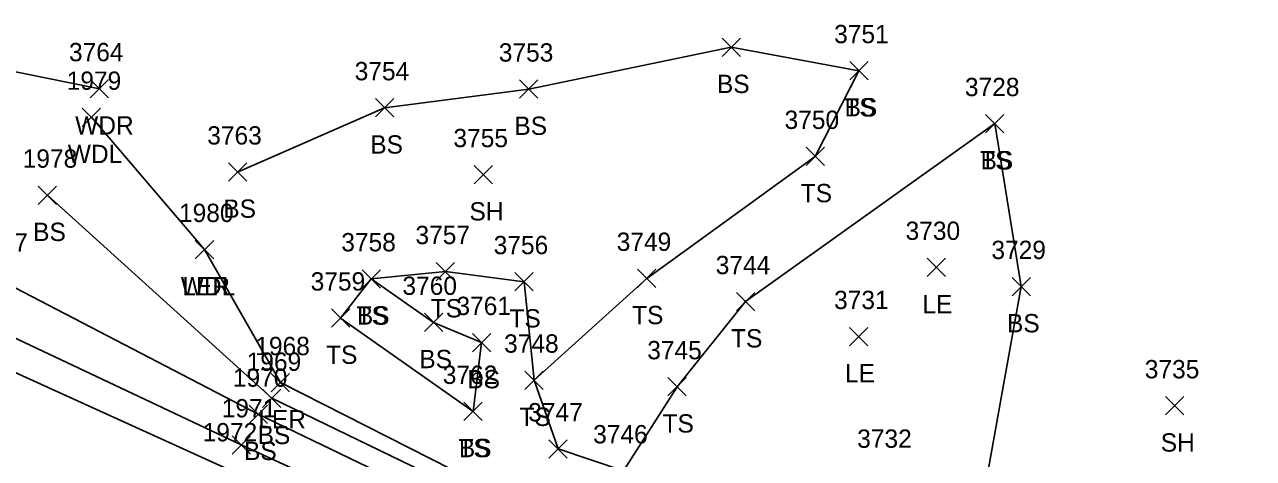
# Model space of a CAD drawing. Extents: x 1599569 to 1610055, y 642560 to 647860.
# Drawn here: x 1601517.7 to 1601651.7, y 647372.7 to 647420 of the extents above; entities that cross this region are included whole.
import ezdxf

# ---------------------------------------------------------------- set-up
doc = ezdxf.new("R2010")
doc.units = 0
for name, color, linetype in [('L_A', 7, 'Continuous'), ('L_I', 7, 'Continuous'), ('L_TIC', 7, 'Continuous'), ('LARO', 7, 'Continuous'), ('LAWA', 7, 'Continuous'), ('LELB', 7, 'Continuous'), ('P_I', 7, 'Continuous'), ('PSP', 7, 'Continuous')]:
    doc.layers.add(name, color=color, linetype=linetype)

msp = doc.modelspace()

# ---------------------------------------------------------------- linework, layer by layer
at = {"layer": 'L_TIC'}
for points in [[(1601593.73, 647416.56), (1601595.73, 647418.56)], [(1601595.73, 647416.56), (1601593.73, 647418.56)], [(1601607.65, 647414), (1601609.65, 647416)], [(1601609.65, 647414), (1601607.65, 647416)], [(1601607.65, 647414), (1601609.65, 647416)], [(1601609.65, 647414), (1601607.65, 647416)], [(1601524.81, 647412.03), (1601526.81, 647414.03)], [(1601526.81, 647412.03), (1601524.81, 647414.03)], [(1601571.64, 647411.99), (1601573.64, 647413.99)], [(1601573.64, 647411.99), (1601571.64, 647413.99)], [(1601555.92, 647409.95), (1601557.92, 647411.95)], [(1601557.92, 647409.95), (1601555.92, 647411.95)], [(1601523.95, 647408.91), (1601525.95, 647410.91)], [(1601525.95, 647408.91), (1601523.95, 647410.91)], [(1601622.48, 647408.22), (1601624.48, 647410.22)], [(1601624.48, 647408.22), (1601622.48, 647410.22)], [(1601622.48, 647408.22), (1601624.48, 647410.22)], [(1601624.48, 647408.22), (1601622.48, 647410.22)], [(1601602.9, 647404.64), (1601604.9, 647406.64)], [(1601604.9, 647404.64), (1601602.9, 647406.64)], [(1601539.89, 647402.94), (1601541.89, 647404.94)], [(1601541.89, 647402.94), (1601539.89, 647404.94)], [(1601566.69, 647402.65), (1601568.69, 647404.65)], [(1601568.69, 647402.65), (1601566.69, 647404.65)], [(1601519.15, 647400.41), (1601521.15, 647402.41)], [(1601521.15, 647400.41), (1601519.15, 647402.41)], [(1601536.28, 647394.48), (1601538.28, 647396.48)], [(1601538.28, 647394.48), (1601536.28, 647396.48)], [(1601536.28, 647394.48), (1601538.28, 647396.48)], [(1601538.28, 647394.48), (1601536.28, 647396.48)], [(1601616.09, 647392.53), (1601618.09, 647394.53)], [(1601618.09, 647392.53), (1601616.09, 647394.53)], [(1601554.46, 647391.28), (1601556.46, 647393.28)], [(1601556.46, 647391.28), (1601554.46, 647393.28)], [(1601554.46, 647391.28), (1601556.46, 647393.28)], [(1601556.46, 647391.28), (1601554.46, 647393.28)], [(1601562.55, 647392.07), (1601564.55, 647394.07)], [(1601564.55, 647392.07), (1601562.55, 647394.07)], [(1601584.51, 647391.33), (1601586.51, 647393.33)], [(1601586.51, 647391.33), (1601584.51, 647393.33)], [(1601571.13, 647390.97), (1601573.13, 647392.97)], [(1601573.13, 647390.97), (1601571.13, 647392.97)], [(1601625.37, 647390.44), (1601627.37, 647392.44)], [(1601627.37, 647390.44), (1601625.37, 647392.44)], [(1601595.3, 647388.79), (1601597.3, 647390.79)], [(1601597.3, 647388.79), (1601595.3, 647390.79)], [(1601551.13, 647387), (1601553.13, 647389)], [(1601553.13, 647387), (1601551.13, 647389)], [(1601561.27, 647386.53), (1601563.27, 647388.53)], [(1601563.27, 647386.53), (1601561.27, 647388.53)], [(1601607.64, 647384.98), (1601609.64, 647386.98)], [(1601609.64, 647384.98), (1601607.64, 647386.98)], [(1601566.5, 647384.33), (1601568.5, 647386.33)], [(1601568.5, 647384.33), (1601566.5, 647386.33)], [(1601544.56, 647379.95), (1601546.56, 647381.95)], [(1601546.56, 647379.95), (1601544.56, 647381.95)], [(1601572.22, 647380.22), (1601574.22, 647382.22)], [(1601574.22, 647380.22), (1601572.22, 647382.22)], [(1601572.22, 647380.22), (1601574.22, 647382.22)], [(1601574.22, 647380.22), (1601572.22, 647382.22)], [(1601587.83, 647379.5), (1601589.83, 647381.5)], [(1601589.83, 647379.5), (1601587.83, 647381.5)], [(1601543.62, 647378.24), (1601545.62, 647380.24)], [(1601545.62, 647378.24), (1601543.62, 647380.24)], [(1601542.15, 647376.5), (1601544.15, 647378.5)], [(1601544.15, 647376.5), (1601542.15, 647378.5)], [(1601565.58, 647376.81), (1601567.58, 647378.81)], [(1601567.58, 647376.81), (1601565.58, 647378.81)], [(1601565.58, 647376.81), (1601567.58, 647378.81)], [(1601567.58, 647376.81), (1601565.58, 647378.81)], [(1601642.1, 647377.42), (1601644.1, 647379.42)], [(1601644.1, 647377.42), (1601642.1, 647379.42)], [(1601540.29, 647373.16), (1601542.29, 647375.16)], [(1601542.29, 647373.16), (1601540.29, 647375.16)], [(1601574.85, 647372.72), (1601576.85, 647374.72)], [(1601576.85, 647372.72), (1601574.85, 647374.72)]]:
    msp.add_lwpolyline(points, dxfattribs=at)
at = {"layer": 'LARO'}
msp.add_lwpolyline([(1601626.48, 647355.02), (1601614.89, 647351.58), (1601573.63, 647366.69), (1601545.56, 647380.95), (1601537.28, 647395.48)], dxfattribs=at)
at = {"layer": 'LAWA'}
for points in [[(1601525.81, 647413.03), (1601511.96, 647415.82), (1601500.19, 647411.74)], [(1601524.95, 647409.91), (1601537.28, 647395.48)]]:
    msp.add_lwpolyline(points, dxfattribs=at)
at = {"layer": 'LELB'}
for points in [[(1601608.65, 647415), (1601594.73, 647417.56), (1601572.64, 647412.99), (1601556.92, 647410.95), (1601540.89, 647403.94)], [(1601573.22, 647381.22), (1601585.51, 647392.33), (1601603.9, 647405.64), (1601608.65, 647415)], [(1601623.48, 647409.22), (1601596.3, 647389.79), (1601588.83, 647380.5), (1601582.98, 647371.32), (1601575.85, 647373.72), (1601573.22, 647381.22), (1601572.13, 647391.97), (1601563.55, 647393.07), (1601555.46, 647392.28), (1601552.13, 647388), (1601566.58, 647377.81)], [(1601623.48, 647409.22), (1601626.37, 647391.44), (1601621.83, 647366.32)], [(1601850.43, 647302.21), (1601817.07, 647284.74), (1601803.58, 647280.33), (1601784.13, 647281.69), (1601758.75, 647290.86), (1601723.07, 647307), (1601685.47, 647323.96), (1601675.62, 647324.78), (1601658.01, 647334.35), (1601634.9, 647343.88), (1601612.64, 647349.36), (1601572.76, 647365.6), (1601544.62, 647379.24), (1601520.15, 647401.41)], [(1601803.11, 647261.21), (1601778.68, 647271.51), (1601755.32, 647284.83), (1601720.1, 647301.53), (1601682.66, 647319.41), (1601674.11, 647321.15), (1601654.95, 647329.02), (1601631.94, 647340.27), (1601610.73, 647346.29), (1601571.98, 647363.61), (1601543.15, 647377.5), (1601514.76, 647392.23)], [(1601555.46, 647392.28), (1601562.27, 647387.53), (1601567.5, 647385.33), (1601566.58, 647377.81)], [(1601677.57, 647312.89), (1601653.54, 647324.67), (1601629.05, 647335.74), (1601609.04, 647344.07), (1601570.72, 647360.58), (1601541.29, 647374.16), (1601512.39, 647387.81)]]:
    msp.add_lwpolyline(points, dxfattribs=at)
at = {"layer": 'PSP'}
msp.add_lwpolyline([(1602119.04, 647109.91), (1602086.42, 647124.41), (1602045.38, 647142.93), (1602000.82, 647163.15), (1601951.88, 647184.91), (1601900.46, 647208.01), (1601848.64, 647231.74), (1601816.21, 647246.31), (1601775.91, 647264.22), (1601751.81, 647275.4), (1601715.81, 647291.56), (1601673.9, 647310.83), (1601638.2, 647326.96), (1601607.44, 647341.11), (1601569.57, 647358.04), (1601539.77, 647371.54), (1601489.48, 647394.4)], dxfattribs=at)

# ---------------------------------------------------------------- texts
at = {"layer": 'L_A'}
for s, p in [('BS', (1601593.17, 647412.56)), ('TS', (1601607.06, 647410)), ('BS', (1601607.09, 647410)), ('WDR', (1601523.17, 647408.03)), ('BS', (1601571.08, 647407.99)), ('BS', (1601555.36, 647405.95)), ('WDL', (1601522.37, 647404.91)), ('TS', (1601621.89, 647404.22)), ('BS', (1601621.92, 647404.22)), ('TS', (1601602.31, 647400.64)), ('BS', (1601539.33, 647398.94)), ('SH', (1601566.18, 647398.65)), ('BS', (1601518.59, 647396.41)), ('WDL', (1601534.69, 647390.48)), ('LER', (1601534.86, 647390.48)), ('LE', (1601615.58, 647388.53)), ('TS', (1601553.87, 647387.28)), ('BS', (1601553.9, 647387.28)), ('TS', (1601561.96, 647388.07)), ('TS', (1601583.92, 647387.33)), ('TS', (1601570.54, 647386.97)), ('BS', (1601624.81, 647386.44)), ('TS', (1601594.71, 647384.79)), ('TS', (1601550.54, 647383)), ('BS', (1601560.71, 647382.53)), ('BS', (1601565.94, 647380.33)), ('LE', (1601607.13, 647380.98)), ('LER', (1601543.14, 647375.95)), ('TS', (1601571.63, 647376.22)), ('TS', (1601571.63, 647376.22)), ('TS', (1601587.24, 647375.5)), ('BS', (1601543.07, 647374.24)), ('BS', (1601541.59, 647372.5)), ('TS', (1601564.98, 647372.81)), ('BS', (1601565.02, 647372.81)), ('SH', (1601641.58, 647373.42))]:
    msp.add_text(s, height=2, dxfattribs=at).set_placement(p)
at = {"layer": 'L_I'}
for s, p in [('3751', (1601605.96, 647418)), ('3751', (1601605.96, 647418)), ('3764', (1601522.5, 647416.03)), ('3753', (1601569.38, 647415.99)), ('3754', (1601553.66, 647413.95)), ('1979', (1601522.25, 647412.91)), ('3728', (1601620.22, 647412.22)), ('3728', (1601620.22, 647412.22)), ('3750', (1601600.55, 647408.64)), ('3763', (1601537.58, 647406.94)), ('3755', (1601564.43, 647406.65)), ('1978', (1601517.45, 647404.41)), ('1980', (1601534.5, 647398.48)), ('1980', (1601534.5, 647398.48)), ('3730', (1601613.75, 647396.53)), ('1977', (1601512.06, 647395.23)), ('3758', (1601552.2, 647395.28)), ('3758', (1601552.2, 647395.28)), ('3757', (1601560.29, 647396.07)), ('3749', (1601582.24, 647395.33)), ('3756', (1601568.82, 647394.97)), ('3729', (1601623.11, 647394.44)), ('3744', (1601593.04, 647392.79)), ('3759', (1601548.86, 647391)), ('3760', (1601558.87, 647390.53)), ('3731', (1601605.95, 647388.98)), ('3761', (1601564.76, 647388.33)), ('1968', (1601542.82, 647383.95)), ('3748', (1601569.96, 647384.22)), ('3748', (1601569.96, 647384.22)), ('3745', (1601585.57, 647383.5)), ('1969', (1601541.88, 647382.24)), ('1970', (1601540.37, 647380.5)), ('3762', (1601563.27, 647380.81)), ('3762', (1601563.27, 647380.81)), ('3735', (1601639.84, 647381.42)), ('1971', (1601539.16, 647377.16)), ('3747', (1601572.59, 647376.72)), ('3746', (1601579.67, 647374.32)), ('3746', (1601579.67, 647374.32)), ('3732', (1601608.47, 647373.84))]:
    msp.add_text(s, height=2, dxfattribs=at).set_placement(p)
at = {"layer": 'P_I'}
msp.add_text('1972', height=2, dxfattribs=at).set_placement((1601537.08, 647374.54))

doc.saveas('drawing.dxf')
